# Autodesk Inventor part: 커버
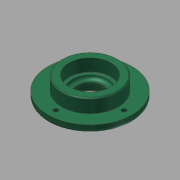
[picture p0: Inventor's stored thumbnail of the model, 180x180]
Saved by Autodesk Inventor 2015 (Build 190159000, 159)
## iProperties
Company: 한국ATC센터
Created: 2014-10
Part Number: 커버
Document SubType Name: Modeling
Designer: KYOUNG IL JANG
Density: 7.86 g/cm^3
Mass: 351.567 g
Surface Area: 161.165 cm^2
Volume: 44.7286 cm^3
Material: 강철, 연강
Appearance: 강철
Author: KYOUNG IL JANG
Revision Number: 1
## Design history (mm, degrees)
sketch "스케치1"
  geometry: C1 r 40 at (0, 0); 1 further point
  constraints: 1 centre point, 1 coincident
  dimensions: "d0" = 80 diameter of C1
extrude "돌출1" new body sketch "스케치1" distance "d1" = 7; taper "d2" = 0 deg
sketch "스케치2"
  geometry: C1 r 27 at (0, 0); 1 further point
  constraints: 1 centre point, 1 coincident
  dimensions: "d3" = 54 diameter of C1
extrude "돌출2" join sketch "스케치2" distance "d4" = 13; taper "d5" = 0 deg
sketch "스케치3"
  geometry: C1 r 20 at (0, 0); 1 further point
  constraints: 1 centre point, 1 coincident
  dimensions: "d6" = 40 diameter of C1
extrude "돌출3" join sketch "스케치3" distance "d7" = 5; taper "d8" = 0 deg
hole "구멍1" diameter "d11" = 25; stored, may be unused: countersink angle "d15" = 90 deg, drill point angle "d17" = 118 deg; dims "d9" = 10, "d10" = 10, "d12" = 6, "d13" = 32, "d14" = 8.3, "d16" = 8
hole "구멍2" diameter "d20" = 34; stored, may be unused: countersink angle "d24" = 90 deg, drill point angle "d26" = 0 deg; dims "d18" = 10, "d19" = 10, "d21" = 6, "d22" = 40, "d23" = 12, "d25" = 3
fillet "모깎기2" dims "d34" = 3
fillet "모깎기1" dims "d27" = 0.3
chamfer "모따기1" distance "d28" = 1; stored, may be unused: second distance "d29" = 2, angle "d30" = 45 deg
chamfer "모따기2" distance "d31" = 1.2; stored, may be unused: second distance "d32" = 2, angle "d33" = 30 deg
sketch "스케치4" dims "d35" = 65
  geometry: 3 further points
  constraints: 2 horizontal alignment, 1 coincident, 2 other
hole "구멍3" sketch "스케치4" at (32.5, 0) diameter "d36" = 4.5; stored, may be unused: countersink angle "d40" = 90 deg, drill point angle "d42" = 118 deg; dims "d37" = 6, "d38" = 8, "d39" = 4.4, "d41" = 13
node "솔리드1"
pattern_circular "원형 패턴1" dims angle "d44" = 360 deg
